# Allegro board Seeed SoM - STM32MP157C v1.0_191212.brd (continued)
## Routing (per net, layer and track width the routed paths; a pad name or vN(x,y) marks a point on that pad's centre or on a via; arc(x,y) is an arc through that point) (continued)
SDMMC3_D1: length 24.5
  TOP w0.089: U3.D9 13.01,15.82 13.01,15.2 12.69,14.88 v1(12.69,14.87)
  LAYER_3 w0.089: v1(19.87,26.53) 19.6,26.26 19.59,26.26 19.56,26.23 19.3,26.23 19.29,26.24 16.89,26.24 16.73,26.41 15,26.41 14.75,26.16 v1(14.5,26.16)
  LAYER_5 w0.089: v1(14.5,26.16) 14.5,25.82 14.41,25.74 13.86,25.74 13.77,25.65 13.77,25.47 13.86,25.38 14.41,25.38 14.5,25.29 14.5,25.11 14.41,25.02 13.86,25.02 13.77,24.94 13.77,24.76 13.86,24.67 14.41,24.67 14.5,24.58 14.5,24.22 13.31,23.03 13.31,22.78 13.4,22.69 13.53,22.69 13.62,22.6 13.62,22.42 13.53,22.33 13.4,22.33 13.31,22.24 13.31,21.99 12.46,21.13 12.46,18.27 13.01,17.72 13.01,15.19 v1(12.69,14.87)
  BOTTOM w0.089: v1(19.87,26.53) 19.87,26.29 19.83,26.24 J2.62
SDMMC3_D2: length 24.5
  TOP w0.089: U3.A7 11.88,20.04 11.33,20.6 11.33,20.91 11.42,21 11.73,21 11.82,21.09 11.82,21.27 11.73,21.36 11.42,21.36 11.33,21.45 11.33,22.76 10.62,23.46 10.62,23.92 10.49,24.05 8.83,24.05 8.74,24.14 8.74,24.46 8.83,24.55 9.63,24.55 9.77,24.69 9.77,25.11 9.86,25.19 10.04,25.19 10.13,25.11 10.13,24.67 10.22,24.58 11,24.58 11.16,24.73 v1(11.16,25.19)
  LAYER_3 w0.089: v1(20.22,24.98) 20.22,24.63 20.07,24.48 11.71,24.48 11.33,24.86 11.33,25.01 v1(11.16,25.19)
  BOTTOM w0.089: J2.64 20.23,24.98 v1(20.22,24.98)
SDMMC3_D3: length 24.5
  TOP w0.089: U3.D10 13.38,14.96 v1(13.49,14.85)
  LAYER_3 w0.089: v1(20.52,26.41) 20.52,26.1 19.82,25.39 19.31,25.39 19.22,25.48 19.22,25.73 19.13,25.82 18.95,25.82 18.86,25.73 18.86,25.48 18.78,25.39 18.6,25.39 18.51,25.48 18.51,25.73 18.42,25.82 18.24,25.82 18.15,25.73 18.15,25.48 18.06,25.39 16.88,25.39 16.79,25.3 16.79,25.17 16.7,25.09 16.52,25.09 16.43,25.17 16.43,25.3 16.35,25.39 16.13,25.39 v1(15.83,25.7)
  LAYER_5 w0.089: v1(15.83,25.7) 15.65,25.52 15.65,25.52 15.19,25.06 15.19,24.79 15.28,24.7 15.38,24.7 15.47,24.61 15.47,24.43 15.38,24.34 15.28,24.34 15.19,24.25 15.19,23.97 14.71,23.49 14.71,21.76 14.62,21.67 14.5,21.67 14.41,21.58 14.41,21.41 14.5,21.32 14.62,21.32 14.71,21.23 14.71,20.89 14.56,20.74 14.1,20.74 14,20.64 14,18.78 14.09,18.69 14.22,18.69 14.3,18.6 14.3,18.42 14.22,18.33 14.09,18.33 14,18.25 14,18.07 14.09,17.98 14.22,17.98 14.3,17.89 14.3,17.71 14.22,17.62 14.09,17.62 14,17.53 14,17.36 14.09,17.27 14.22,17.27 14.3,17.18 14.3,17 14.22,16.91 14.09,16.91 14,16.82 14,15.7 13.49,15.19 v1(13.49,14.85)
  BOTTOM w0.089: v1(20.52,26.41) 20.52,26.16 20.63,26.05 20.63,25.76 20.48,25.61 20.48,25.41 20.63,25.26 J2.66
SPI1_CLK: length 32.7
  TOP w0.076: v1(9.07,30.24) 8.83,30.24 8.75,30.17 8.41,30.17
  TOP w0.089: U3.G3 9.63,14.7 8,14.7 5.39,17.31 5.39,27.37 4.96,27.8 4.96,29.45 5.67,30.17 8.41,30.17
  BOTTOM w0.089: J2.40 15.43,24.79 13.57,26.65 13.57,28.85 13.09,29.33 11.54,29.33 11.33,29.53 9.78,29.53 v1(9.07,30.24)
SPI1_MISO: length 26.2
  TOP w0.089: U3.G1 7.99,14.45 5.21,17.24 5.21,25.81 v1(4.85,26.18)
  LAYER_3 w0.089: v1(13.21,26.78) 12.59,27.4 9.43,27.4 8.59,26.56 7.27,26.56 6.89,26.18 v1(4.85,26.18)
  BOTTOM w0.089: v1(13.21,26.78) 13.38,26.61 13.38,26.57 15.03,24.92 J2.38
SPI1_MOSI: length 21
  TOP w0.089: v1(11.02,13.79) 10.86,13.79 10.52,13.45 U3.J4
  LAYER_5 w0.089: v1(10.21,26.86) 10.21,26.52 10.25,26.48 10.25,26.26 9.74,25.75 9.74,24.71 9.25,24.22 9.25,21.46 9.66,21.05 9.66,20.06 9.48,19.88 9.48,18.46 10.01,17.92 10.01,14.8 v1(11.02,13.79)
  BOTTOM w0.089: J2.36 14.63,25.04 13.44,26.23 10.84,26.23 v1(10.21,26.86)
SPI5_CLK: length 26.8
  TOP w0.089: U3.Y11 13.71,8.13 13.71,8.26 v1(13.78,8.33)
  LAYER_5 w0.089: v1(13.78,8.33) 13.96,8.16 13.96,8.03 14.46,7.53 18.11,7.53 18.93,8.35 18.93,9.04 19.21,9.32 19.21,16.81 18.37,17.64 18.37,20.88 17.95,21.3 17.3,21.3 16.95,21.65 16.95,25.57 v1(17.13,25.75)
  BOTTOM w0.089: J2.46 16.63,25.23 16.95,25.55 16.95,25.57 v1(17.13,25.75)
SPI5_MISO: length 27.1
  TOP w0.089: U3.W4 v2(10.37,8.45)
  GND02 w0.089: v1(9.59,5.14) 9.59,5.38 9.6,5.4 9.6,7.68 v2(10.37,8.45)
  LAYER_6 w0.089: v1(16.09,23.08) 16.09,18.16 13.11,15.18 13.11,14.21 12.86,13.96 11.6,13.96 11.46,14.1 10.81,14.1 9.59,12.87 v1(9.59,5.14)
  BOTTOM w0.089: v1(16.09,23.08) 16.09,23.33 16.23,23.46 J2.44
SPI5_MOSI: length 24.8
  TOP w0.089: v1(15.13,8.37) 15.13,8.13 15.13,8.12 15.13,7.7 U3.AA14
  LAYER_5 w0.089: v1(15.13,8.37) 15.3,8.2 15.32,8.2 15.55,7.97 18.04,7.97 18.57,8.5 18.57,9.19 18.85,9.47 18.85,16.48 17.86,17.47 17.86,18.18 16.72,19.32 16.72,25.46 16.68,25.49 v1(16.68,25.74)
  BOTTOM w0.089: v1(16.68,25.74) 16.51,25.56 16.51,25.47 15.83,24.79 J2.42
STLINK_SWCLK: length 32.1
  TOP w0.089: U3.B20 18.63,17.2 18.63,17.9 18.63,17.91 18.63,18.79 19.37,19.53 19.37,20.35 19.54,20.52 19.54,20.89 20.27,21.63 21.01,21.63 21.75,22.37 21.75,24.48 22.1,24.83 22.1,26.97 20.1,28.97 20.1,32.02 19.59,32.53 19.59,34.43 19.08,34.94 12.26,34.94 11.75,34.43 10.95,34.43 v1(10.7,34.69)
  BOTTOM w0.089: v1(10.7,34.69) 11.02,34.36 J4.54
STLINK_SWDIO: length 32.2
  TOP w0.089: U3.C20 18.63,16.7 18.98,16.7 19.13,16.85 19.13,17.79 19.31,17.97 19.31,19.09 20.02,19.8 20.02,20.48 20.18,20.64 20.18,21.16 20.43,21.4 21.09,21.4 21.95,22.27 21.95,24.43 22.28,24.76 22.28,28.31 20.48,30.12 20.48,31.89 19.84,32.53 19.84,34.43 19.08,35.2 11.86,35.2 v1(11.42,34.75)
  BOTTOM w0.089: J4.52 v1(11.42,34.75)
STUSB1600_IRQOUTN: length 16.8
  TOP w0.089: v1(11.31,10.76) 11.11,10.95 U3.P4
  LAYER_5 w0.089: v1(11.31,10.76) 11.06,10.76 10.42,11.4 10.42,11.86 9.15,13.13 9.15,16.32 8.16,17.31 8.16,19.57 8.03,19.7 8.03,20.06 7.55,20.54 7.55,22.8 v1(7.78,23.03)
  BOTTOM w0.089: v1(7.78,23.03) 8.63,23.88 J2.6
TIM4_CH3: length 38.3
  TOP w0.089: U3.L3 9.63,12.21 7.28,12.21 v1(7.22,12.14)
  LAYER_3 w0.089: v1(14.74,34.08) 14.36,34.46 14.1,34.46 13.77,34.13 13.77,33.9 13.16,33.29 5.47,33.29 5.03,32.86 3.92,32.86 v1(3.69,32.63)
  LAYER_5 w0.089: v1(3.69,32.63) 4.09,32.22 4.09,22.95 5.01,22.04 5.01,16.53 5.71,15.83 5.71,13.65 v1(7.22,12.14)
  BOTTOM w0.089: v1(14.74,34.08) 14.74,33.83 14.62,33.71 J4.36
TIM4_CH4: length 33.8
  TOP w0.089: U3.J2 7.8,13.45 7.75,13.5 7.53,13.5 v1(7.35,13.69)
  LAYER_3 w0.089: v1(4.81,32.53) 6.41,32.53 6.99,33.11 13.26,33.11 v1(14.23,34.08)
  LAYER_5 w0.089: v1(7.35,13.69) 6.84,14.2 6.84,15.28 5.39,16.73 5.39,22.27 4.5,23.16 4.5,32.22 v1(4.81,32.53)
  BOTTOM w0.089: v1(14.23,34.08) 14.23,33.83 14.22,33.82 J4.38
USART1_CTS: length 27.1
  TOP w0.089: v1(11.08,15.08) 10.59,14.58 10.51,14.58 U3.G4
  LAYER_3 w0.089: v1(18.7,27.45) 18.7,27.7 18.39,28 17.74,28 17.74,28.01 10.62,28.01 v1(10.44,28.18)
  LAYER_5 w0.089: v1(10.44,28.18) 10.8,28.18 11.49,27.5 11.49,26.89 11.47,26.87 11.47,23.82 11.21,23.56 11.21,22.38 11.75,21.84 11.75,19.43 11.36,19.05 11.36,15.36 v1(11.08,15.08)
  BOTTOM w0.089: J2.56 18.63,26.89 18.7,26.96 v1(18.7,27.45)
USART1_RTS: length 45.1
  TOP w0.089: v1(1.88,31.79) 1.88,23.84 4.65,21.07 4.65,16.88 7.88,13.66 9.08,13.66 U3.H2
  LAYER_3 w0.089: v1(1.88,31.79) 5.79,31.79 7.44,30.14 8.18,30.14 9.39,28.93 18.48,28.93 19.42,27.99 19.42,27.73 19.44,27.72 v1(19.44,27.47)
  BOTTOM w0.076: 19.08,26.81 19.03,26.76 19.03,25.87
  BOTTOM w0.089: v1(19.44,27.47) 19.44,27.21 19.25,27.02 19.25,26.98 19.08,26.81 ; 19.03,25.87 J2.58
USART1_RX: length 43.5
  TOP w0.089: U3.H1 7.86,13.95 4.86,16.96 4.86,22.12 2.21,24.76 2.21,30.86 2.2,30.88 v1(2.2,31.13)
  LAYER_3 w0.089: v1(18.29,27.14) 18.95,27.14 19.11,27.3 19.11,27.88 18.79,28.2 18.09,28.2 18.06,28.17 17.81,28.17 17.78,28.2 11.28,28.2 10.93,28.55 9.39,28.55 8.03,29.91 7.22,29.91 6.06,31.07 5.62,31.07 5.18,31.51 2.33,31.51 2.2,31.38 v1(2.2,31.13)
  BOTTOM w0.089: J2.54 18.23,26.66 18.22,26.67 18.22,26.82 18.29,26.9 v1(18.29,27.14)
USART1_TX: length 26.9
  TOP w0.089: v1(11.28,14.44) 11.05,14.21 11.05,14.21 10.97,14.13 10.92,14.13 10.49,13.7 10.13,13.7 U3.J3
  LAYER_5 w0.089: v1(11.28,14.44) 10.75,14.44 10.29,14.91 10.29,20.67 9.43,21.53 9.43,24.12 9.92,24.61 9.92,25.63 10.69,26.4 10.69,26.74 10.6,26.84 v1(10.6,27.09)
  LAYER_6 w0.089: v1(10.6,27.09) 10.84,27.09 11.03,27.27 17.68,27.27 v1(17.99,27.58)
  BOTTOM w0.089: J2.52 17.83,24.79 17.99,24.95 v1(17.99,27.58)
USART2_RX: length 9.4
  TOP w0.089: v1(7.87,22.32) 7.7,22.14 7.7,22.14 6.63,21.07 6.63,19.62 6.42,19.41 6.42,18.56 7.87,17.11 7.87,16.49 8.15,16.21 9.13,16.21 U3.D2
  BOTTOM w0.089: v1(7.87,22.32) 7.87,22.26 7.83,22.22 J2.1
USART2_TX: length 21.9
  TOP w0.089: U3.D7 v1(11.88,15.65)
  LAYER_3 w0.089: v1(7.15,25.96) 7.32,26.13 11.16,26.13 11.59,26.57 11.59,26.61 v1(11.77,26.79)
  LAYER_5 w0.089: v1(11.88,15.65) 12.11,15.88 12.11,21.36 12.32,21.58 12.32,22.45 12.49,22.62 12.49,25.41 11.77,26.13 v1(11.77,26.79) ; v1(7.15,25.96) 7.15,25.71 8.51,24.35 v1(8.51,23.32)
  BOTTOM w0.089: J2.3 8.23,22.79 8.51,23.07 v1(8.51,23.32)
USB1_N: length 72.3
  TOP w0.089: U3.AB17 16.63,6.71 16.63,5.77 17.91,4.49 17.91,4.13
  TOP w0.114: v1(17.71,2.1) 17.91,2.3 17.91,4.13
  LAYER_6 w0.135: v1(17.71,2.1) 17.9,1.92 17.9,1.24 18.46,0.68 23.17,0.68 24.08,1.58 25.81,1.58 30,5.77 30,18.29 31.18,19.47 31.18,30.96 28.15,33.98 24.39,33.98 22.84,35.53 9.57,35.53 9.35,35.76 9.35,36.23 v1(9.53,36.41)
  BOTTOM w0.114: J4.61 9.42,35.82 9.36,35.88 9.36,36.24 v1(9.53,36.41)
USB1_P: length 72.2
  TOP w0.089: 18.22,4.16 18.22,4.54 17.79,4.96 17.79,5.09 17.94,5.24 17.94,5.32 17.76,5.5 17.63,5.5 17.5,5.37 17.38,5.37 16.88,5.87 U3.AC17
  TOP w0.114: 18.22,4.16 18.19,4.13 18.19,2.3 v1(18.39,2.1)
  LAYER_6 w0.135: v1(8.85,36.41) 9.03,36.23 9.03,35.63 9.44,35.22 9.79,35.22 10.01,34.99 10.32,34.99 10.55,35.22 11.74,35.22 11.88,35.09 11.88,34.9 12.01,34.76 12.28,34.76 12.42,34.9 12.42,35.09 12.55,35.22 13.22,35.22 13.45,34.99 13.76,34.99 13.99,35.22 22.71,35.22 24.26,33.67 28.02,33.67 30.87,30.83 30.87,19.6 29.69,18.42 29.69,5.9 25.68,1.9 23.95,1.9 23.04,0.99 18.59,0.99 18.21,1.37 18.21,1.92 v1(18.39,2.1)
  BOTTOM w0.114: v1(8.85,36.41) 9.08,36.18 9.08,35.88 9.02,35.82 J4.63
USB2_N: length 72.2
  TOP w0.089: U3.AB16 16.12,6.69 16.12,5.29 16.95,4.46 16.95,4.11
  TOP w0.114: v1(19.03,1.36) 18.9,1.5 17.31,1.5 16.95,1.86 16.95,4.11
  LAYER_6 w0.135: v1(19.03,1.36) 19.18,1.51 21.15,1.51 21.98,2.34 21.98,6.6 20.59,7.99 20.59,16.45 22.51,18.37 26.98,18.37 29.68,21.07 29.68,28.87 25.81,32.74 14.09,32.74 14.08,32.74 9.01,32.74 8.2,33.56 8.2,36.23 v1(8.38,36.41)
  BOTTOM w0.114: J4.67 8.22,35.82 8.16,35.88 8.16,36.19 v1(8.38,36.41)
USB2_P: length 72.1
  TOP w0.089: U3.AC16 16.38,5.38 17.23,4.54 17.23,4.41
  TOP w0.114: 17.23,4.41 17.23,3.95 17.3,3.88 17.51,3.88 17.59,3.8 17.59,3.5 17.51,3.42 17.35,3.42 17.23,3.29 17.23,3.06 17.3,2.99 17.48,2.99 17.58,2.89 17.58,2.61 17.51,2.53 17.37,2.53 17.23,2.39 17.23,1.97 17.42,1.77 18.86,1.77 v1(19.02,1.93)
  LAYER_6 w0.135: v1(7.7,36.41) 7.88,36.23 7.88,35.4 7.75,35.27 7.58,35.27 7.45,35.13 7.45,34.87 7.58,34.73 7.75,34.73 7.88,34.6 7.88,33.43 8.88,32.43 13.96,32.43 13.96,32.43 25.68,32.43 29.37,28.74 29.37,21.2 26.85,18.69 22.38,18.69 20.28,16.58 20.28,7.86 21.66,6.48 21.66,2.47 21.02,1.83 19.12,1.83 v1(19.02,1.93)
  BOTTOM w0.114: v1(7.7,36.41) 7.88,36.23 7.88,35.88 7.82,35.82 J4.69
VREF+: length 36.8
  TOP w0.203: U3.R4 10.7,10.45 v1(10.75,10.4)
  PWR_4 w0.305: v1(15.17,34.16) 15.17,33.8 14.66,33.29 12.22,33.29 11.33,32.4 11.33,28.34 10.7,27.7 9.55,27.7 9.17,27.32 9.17,26.37 7.24,24.43 7.24,20.95 9.07,19.11 9.07,18.58 9.81,17.85 9.81,10.91 10.32,10.4 v1(10.75,10.4)
  BOTTOM w0.203: J4.31 15.42,34.45 15.39,34.42 15.39,34.38 v1(15.17,34.16)
  BOTTOM w0.254: v1(10.75,10.4) 10.75,10.43
  BOTTOM w0.381: 10.19,10.43 10.73,10.43 v1(10.75,10.4) ; 10.19,10.43 10.06,10.3 R94.2 ; 10.19,10.43 10.29,10.53 C47.1
VREF_DDR: length 50.4
  TOP w0.152: v1(33.52,29.64) U2.16
  TOP w0.203: v1(18.47,5.96) 18.38,6.05 U3.AC20
  TOP w0.305: U6.H1 30.28,17.02 30.46,17.21 v3(30.46,17.61) ; U6.M8 v1(26.67,9.03)
  TOP w0.381: v1(33.52,29.64) 33.81,29.35 C201.1 ; v1(26.9,6.21) 26.95,6.16 C53.1 ; C54.1 30.13,18 30.46,17.67 v3(30.46,17.61)
  LAYER_5 w0.381: v1(33.52,29.64) 33.52,20.3 31.15,17.93 30.77,17.93 v3(30.46,17.61) 30.14,17.3 30.14,11.64 27.51,9.01 ; 27.51,9.01 27.51,6.82 v1(26.9,6.21) 26.62,5.93 26.62,3.14 24.55,1.07 21.89,1.07 v1(21.61,1.35) ; 27.51,9.01 27.49,9.03 v1(26.67,9.03)
  BOTTOM w0.381: v1(21.61,1.35) 20.26,1.35 19.03,2.58 19.03,3.81 19.11,3.89 19.11,5.22 18.72,5.61 C27.1 18.47,5.63 v1(18.47,5.96)
VTT_DDR: length 78.9
  TOP w0.152: U2.14 33.43,28.84
  TOP w0.381: v1(35.46,27.66) 34.88,28.24 C202.1 34.32,28.27 33.75,28.84 33.43,28.84 ; R38.2 29.87,4.56 v1(29.67,4.36)
  LAYER_5 w0.381: v1(33.56,16.91) 33.95,16.91 34.12,16.74 36.29,16.74 36.89,16.15 36.89,6.09 35.72,4.92 30.23,4.92 v1(29.67,4.36)
  BOTTOM w0.381: R24.2 R22.2 R19.2 ; R24.2 C63.1 ; R24.2 R26.2 ; R19.2 C61.1 C59.1 ; R19.2 R17.2 ; R29.2 R119.2 R27.2 ; R29.2 28.1,6.07 27.71,5.69 C69.1 ; R29.2 R33.2 R18.2 R21.2 25.07,6.74 ; R20.2 R32.2 R40.2 ; R20.2 27.54,17.32 C62.1 ; R20.2 R17.2 ; 25.07,6.74 25.07,6.29 25.05,6.26 C60.1 C67.1 C69.1 ; 25.07,6.74 R28.2 R23.2 R25.2 ; R40.2 29.45,17.32 29.44,17.32 C68.1 C62.1 ; R40.2 R37.2 R39.2 R36.2 R35.2 v1(33.56,16.91) R34.2 33.94,17.32 33.94,17.32 C70.1 32.87,17.89 32.59,18.17 C93.1 C94.1 32.59,20.13 35.46,23 v1(35.46,27.66) ; C69.1 C66.1 29.48,5.23 C91.1 29.67,4.36 v1(29.67,4.36) 29.67,4.36 C92.1 ; R30.2 R26.2 ; R26.2 22.97,17.32 22.89,17.39 C65.1 ; R25.2 R31.2 ; R25.2 22.76,6.34 23.27,5.83 C64.1 ; R17.2 26.58,17.32 C59.1 ; C62.1 C59.1
N3275089: length 4.3
  TOP w0.127: R13.1 27.91,5.52 27.49,5.94 27.49,9.04 U6.L8
N3282469: length 9.2
  TOP w0.089: v1(5.85,35.47) 6.61,35.47 9.99,32.1 9.99,30.42 10.79,29.62 U8.A6
  BOTTOM w0.089: v1(5.85,35.47) 5.6,35.47 5.55,35.53 R147.1
N3282544: length 1.9
  TOP w0.089: U8.C2 12.25,27.37 12.25,26.78 v1(12.27,26.76)
  BOTTOM w0.089: v1(12.27,26.76) 12.27,27.3 12.48,27.5 C180.1
N3283232: length 10.2
  TOP w0.076: U8.A3 10.81,28.12 10.57,27.88 10.32,27.88 8.59,29.61
  TOP w0.089: v1(5.85,26.51) 5.85,29.02 6.43,29.61 8.59,29.61
  BOTTOM w0.089: v1(5.85,26.51) 5.35,26.51 R136.2 4.69,26.49 4.68,26.5 R125.2
N3283236: length 7.3
  TOP w0.076: 10.05,28.63 10.63,28.63 10.64,28.62 U8.A4
  TOP w0.089: 10.05,28.63 8.72,29.96 6.22,29.96 6.09,29.84 v1(5.85,29.84)
  BOTTOM w0.089: v1(5.85,29.84) 5.82,29.81 5.7,29.81 5.67,29.84 R137.2 4.69,29.84 4.68,29.85 R126.2
N3283240: length 9.1
  TOP w0.076: U8.A5 10.73,29.12 10.44,29.4
  TOP w0.089: v1(5.77,32.91) 8.39,32.91 9.58,31.72 9.58,30.27 10.44,29.4
  BOTTOM w0.089: v1(5.77,32.91) 5.73,32.91 5.7,32.93 R138.2 4.69,32.93 4.68,32.94 R127.2
N3283244: length 13.4
  TOP w0.076: 9.31,28.29 10.23,27.38 11.26,27.38 U8.B2
  TOP w0.089: 9.31,28.29 8.38,29.23 6.89,29.23 6.35,28.69 6.35,23.74 v1(6.15,23.54)
  BOTTOM w0.089: v1(6.15,23.54) 5.9,23.54 5.72,23.35 R139.2 4.69,23.35 4.68,23.34 R128.2
N3283248: length 12
  TOP w0.076: U8.B3 11.25,27.86 10.9,27.86 10.72,27.68 10.59,27.68
  TOP w0.089: v1(5.87,24.96) 6.18,25.26 6.18,28.87 6.74,29.43 8.54,29.43 10.3,27.68 10.59,27.68
  BOTTOM w0.089: v1(5.87,24.96) 5.83,24.92 R140.2 4.7,24.92 4.68,24.9 R129.2
N3283252: length 8.9
  TOP w0.076: U8.B4 11.25,28.36 10.68,28.36 10.57,28.48 10.3,28.48 10.29,28.46 9.99,28.46 8.67,29.78 8.41,29.78
  TOP w0.089: 8.41,29.78 6.3,29.78 6.17,29.66 6.16,29.66 5.29,28.79 v1(5.29,28.54)
  BOTTOM w0.089: R130.2 4.68,28.12 4.7,28.14 R141.2 v1(5.29,28.54)
N3283256: length 9.6
  TOP w0.076: 9.91,29.05 10.18,28.78 10.83,28.78 10.9,28.86 11.25,28.86 U8.B5
  TOP w0.089: 9.91,29.05 9.38,29.58 9.38,31.31 9.12,31.56 5.92,31.56 v1(5.74,31.39)
  BOTTOM w0.089: v1(5.74,31.39) 5.72,31.39 5.69,31.36 R142.2 4.96,31.36 4.92,31.41 R131.2
N3283260: length 10.3
  TOP w0.076: 9.78,30.34 10.75,29.38 11.26,29.38 U8.B6
  TOP w0.089: v1(5.87,34.56) 7.07,34.56 9.78,31.84 9.78,30.34
  BOTTOM w0.089: R132.2 4.65,34.59 4.66,34.58 R143.2 5.85,34.58 v1(5.87,34.56)
N3283264: length 13.6
  TOP w0.076: U8.M5 16.28,29.12 15.95,28.79 15.93,28.79 v1(15.76,28.62)
  BOTTOM w0.076: 17.15,29.96 17.07,29.96 16.98,29.87 16.98,29.76 17.2,29.54 17.2,29.43 17.1,29.32 16.99,29.32 16.77,29.55 16.66,29.55 16.55,29.44 16.55,29.33 16.77,29.11 16.77,29 16.66,28.89 16.56,28.89 16.33,29.12 16.23,29.12 15.93,28.82 15.93,28.79 v1(15.76,28.62)
  BOTTOM w0.089: R133.2 R144.2 21.46,27.78 21.37,27.87 21.37,28.12 21.28,28.21 20.9,28.21 20.81,28.3 20.81,28.48 20.9,28.57 21.28,28.57 21.37,28.66 21.37,29.56 20.96,29.96 19.59,29.96 19.5,29.87 19.5,29.75 19.41,29.66 19.23,29.66 19.14,29.75 19.14,29.87 19.05,29.96 18.87,29.96 18.79,29.87 18.79,29.75 18.7,29.66 18.52,29.66 18.43,29.75 18.43,29.87 18.34,29.96 17.15,29.96
N3283268: length 37.4
  TOP w0.076: v1(15.98,29.4) 16.15,29.57 16.17,29.57 16.22,29.62 U8.M6
  BOTTOM w0.089: 21.7,29.63 21.06,30.27 20.38,30.27 20.29,30.36 20.29,30.92 20.2,31 20.03,31 19.94,30.92 19.94,30.36 19.85,30.27 16.85,30.27 v1(15.98,29.4) ; 21.7,29.63 21.74,29.58 21.74,29.5 ; 21.7,29.63 21.87,29.63 ; R145.2 21.74,29.5 ; 21.74,29.5 21.87,29.63 ; 21.87,29.63 22.69,29.63 22.89,29.43 22.89,28.69 22.98,28.6 23.23,28.6 23.32,28.51 23.32,28.33 23.23,28.24 22.98,28.24 22.89,28.15 22.89,27.98 22.98,27.89 23.23,27.89 23.32,27.8 23.32,27.62 23.23,27.53 22.98,27.53 22.89,27.44 22.89,27.26 22.98,27.18 23.23,27.18 23.32,27.09 23.32,26.91 23.23,26.82 22.98,26.82 22.89,26.73 22.89,26.55 22.98,26.46 23.23,26.46 23.32,26.38 23.32,26.2 23.23,26.11 22.98,26.11 22.89,26.02 22.89,25.84 22.98,25.75 23.23,25.75 23.32,25.66 23.32,25.49 23.23,25.4 22.98,25.4 22.89,25.31 22.89,25.13 22.98,25.04 23.23,25.04 23.32,24.95 23.32,24.78 23.23,24.69 22.98,24.69 22.89,24.6 22.89,24.42 22.98,24.33 23.23,24.33 23.32,24.24 23.32,24.06 23.23,23.98 22.98,23.98 22.89,23.89 22.89,23.71 22.98,23.62 23.23,23.62 23.32,23.53 23.32,23.35 23.23,23.26 22.98,23.26 22.89,23.18 22.89,23 22.98,22.91 23.23,22.91 23.32,22.82 23.32,22.64 23.23,22.55 22.98,22.55 22.89,22.46 22.89,21.58 22.2,20.89 21.7,20.89 21.37,20.56 20.86,20.56 19.36,19.07 17.99,19.07 17.63,18.7 17.63,18.7 16.67,17.75 15.9,17.75 15.42,17.26 13.82,17.26 13.14,16.58 C179.1 R134.2
N3283272: length 2.4
  TOP w0.089: U8.K5 15.5,28.88 v1(15.24,28.62)
  BOTTOM w0.089: v1(15.24,28.62) 15.24,28.37 15.35,28.27 R146.2 R135.2
N3285898: length 1.2
  TOP w0.076: v1(14.97,29.45) 15,29.42 U8.J5
  BOTTOM w0.076: v1(14.97,29.45) 14.79,29.63 14.79,29.73 14.66,29.86 R148.1
N3300775: length 1.1
  TOP w0.152: 29.87,26.81 30.07,27.01 U2.7
N3300820: length 2.5
  TOP w0.381: v1(28.16,23.58) R154.1 v1(27.55,24.18) ; v1(28.76,24.02) 28.95,24.21 L9.2
N3300941: length 0.8
  TOP w0.152: U2.11 31.68,27.29 31.9,27.07
N3301067: length 1.1
  TOP w0.152: 29.75,33.8 29.68,33.73 U2.29
N3301183: length 1.1
  TOP w0.152: U2.25 31.28,33.79
N3302965: length 1.4
  TOP w0.152: U2.40 v1(26.32,30.04)
  BOTTOM w0.381: C208.1 26.5,29.86 v1(26.32,30.04)
N3306561: length 4.4
  TOP w0.089: R153.2 25,25.64 25.3,25.95 25.3,26.74 25.84,27.27 27.46,27.27 27.68,27.48 U2.1
N3308705: length 1.1
  TOP w0.152: U2.33 28.07,33.44 27.84,33.67
N3308709:
  vias: v1(25.3,36.72) v1(25.81,36.72) v1(26.32,36.72) v1(26.83,36.72)
N3309141: length 2.5
  TOP w0.152: 26.37,32.22 26.45,32.22 26.63,32.04 U2.35
  TOP w0.381: R155.1 25.51,33.09 26.37,32.22
N3309849: length 2.1
  TOP w0.152: 26.38,31.2 26.42,31.24 U2.37
  TOP w0.381: R150.2 24.87,31.08 24.92,31.13 25.31,31.13 25.37,31.2 26.38,31.2
N3309984: length 2.4
  TOP w0.152: U2.38 25.52,30.84 25.3,30.62
  TOP w0.381: 25.3,30.62 25.3,30.61 R156.1
N3317349: length 4.5
  TOP w0.203: U3.AB15 15.88,4.51 16.34,4.05 v1(16.34,3.19)
  BOTTOM w0.203: C48.2 16.21,3.19 16.21,3.19 v1(16.34,3.19)
N3317353: length 31.9
  TOP w0.089: U3.AB14 15.65,6.69 15.65,4.34 16.03,3.96 16.03,2.18 v1(16.29,1.92) ; 14.84,15.56 15.02,15.56 15.13,15.68 15.13,16.21 U3.C14
  TOP w0.203: v1(14.39,15.54) 14.81,15.54 14.84,15.56
  LAYER_6 w0.089: v1(16.29,1.92) 16.02,2.19 16.02,3.94 15.83,4.13 14.99,4.13 14.25,3.39 11.97,3.39 9.78,5.58 9.78,10.56 10.22,10.99 10.9,10.99 11.76,11.85 11.76,13.38 12.15,13.76 13.19,13.76 13.39,13.96 13.62,13.96 14.2,14.54 14.5,14.54 14.58,14.63 14.58,15.35 v1(14.39,15.54)
  BOTTOM w0.381: C49.1 14.08,15.54 v1(14.39,15.54) 14.69,15.54 C50.1 14.79,16.43 R95.2
N3322011: length 2.3
  TOP w0.089: U3.C18 17.15,16.45 v1(17.12,16.48) 17.1,16.45 U3.C17
  BOTTOM w0.203: C142.1 C51.1 17.18,16.09 17.12,16.15 v1(17.12,16.48)
N3340590: length 8.8
  TOP w0.203: v1(11.12,8.35) 11.12,8.83 11.35,9.06 11.35,9.57 U3.1H1
  TOP w0.254: v1(10.78,4.11) 11.12,4.11 L5.2
  BOTTOM w0.203: v1(11.12,8.35) 11.12,7.74 10.83,7.44 R94.1
  BOTTOM w0.254: C46.1 11.31,9.06 11.21,8.96 11.21,8.83 11.12,8.75 v1(11.12,8.35)
  BOTTOM w0.381: R94.1 10.83,5.28 10.78,5.23 v1(10.78,4.11) 10.62,3.95 R93.2
N3340594: length 1.2
  TOP w0.381: L5.1 12.04,2.58 12.13,2.49 R12.2
N3362916: length 2
  TOP w0.089: R10.1 21.36,12.84 21.11,13.09 20.02,13.09 U3.K23
N3364394: length 3.9
  TOP w0.089: v1(19.28,5.86) 19.04,5.86 18.63,6.26 18.63,7.12 18.55,7.21 18.28,7.21 18.13,7.35 18.13,7.7 U3.Y19
  BOTTOM w0.089: TP102.1 19.37,5.48 19.28,5.57 v1(19.28,5.86)
N3364398: length 1.1
  TOP w0.089: U3.K20 v1(18.07,12.95)
  BOTTOM w0.127: TP103.1 18.19,13.07 v1(18.07,12.95)
N3364402: length 5.4
  TOP w0.089: v1(17.63,12.94) 17.63,12.31 17.76,12.18 17.83,12.18 18.23,12.18 18.25,12.21 18.63,12.21 U3.L21
  BOTTOM w0.089: v1(17.63,12.94) 17.63,12.7 17.63,12.69 17.63,12.39 17.86,12.16 19.42,12.16 19.73,11.85 TP104.1
N3371131: length 4
  TOP w0.127: OSC1.3 2.1,5.57 3.13,4.54 3.75,4.54 4.07,4.22 C108.1 R4.1
N3371139: length 2.8
  TOP w0.127: OSC1.4 4.54,5.57 4.91,5.2 5.22,5.2 5.22,5.19 v1(5.49,5.19)
  BOTTOM w0.127: v1(5.49,5.19) 5.49,5.02 5.57,4.94 C106.2 R87.2
N3371143: length 4.2
  TOP w0.127: R1.2 4.05,9.42 4.06,9.43 R90.1 3.54,9.77 3.47,9.7 R88.2 ; R1.2 3.77,8.76 3.76,8.75 C107.2 ; R1.2 4.05,8.27 4.28,8.04 OSC1.1
N3374325: length 4.9
  TOP w0.089: U3.AB13 14.63,6.71 14.63,5.81 14.89,5.55 v1(14.89,3.59)
  BOTTOM w0.127: R81.1 R82.1 v1(14.89,3.59)
N3375018: length 7
  TOP w0.089: 6.79,10.56 7.19,10.96 7.47,10.96 7.73,10.71 9.63,10.71 U3.R3
  TOP w0.127: v1(6.15,8.33) 6.15,8.6 6.79,9.24 6.79,10.56
  BOTTOM w0.127: R85.2 v1(6.15,8.33) 6.13,8.31 R83.1
N3375025: length 7.8
  TOP w0.089: v1(6.02,5.99) 6.58,6.54 6.58,7.51 6.96,7.89 6.96,9.13 7.55,9.72 7.96,9.72 7.98,9.7 9.63,9.7 U3.T3
  BOTTOM w0.127: R86.2 6.05,6.01 v1(6.02,5.99) 6.02,5.99 R84.1
N3375486: length 1.1
  TOP w0.203: v1(11.06,11.9) 10.43,11.9 U3.M4
  BOTTOM w0.203: C105.1 11.26,11.95 11.21,11.9 v1(11.06,11.9)
N3376367: length 1.4
  TOP w0.089: U3.AB18 17.56,6.78 v1(17.56,5.96)
  BOTTOM w0.089: R80.1 v1(17.56,5.96)
N3444553: length 4
  TOP w0.127: R2.2 4.66,14.2 4.47,14.02 4.47,13.6 4.28,13.41 C109.1 3.38,13.41 2.83,13.95 2.83,14.03 2.42,14.44 X1.1
N3444560: length 4.4
  TOP w0.127: X1.2 2.04,11.87 2.63,12.46 C110.1 4.33,12.46 4.45,12.35 4.45,11.79 4.58,11.66 R79.1
N3457313: length 4.8
  TOP w0.089: U3.N3 v2(9.87,11.45)
  GND02 w0.089: v1(6.31,11.23) 6.48,11.06 8.56,11.06 8.95,11.45 v2(9.87,11.45)
  BOTTOM w0.089: v1(6.31,11.23) 6.48,11.06 6.48,11.05 6.58,10.95 TP101.1
N3836449: length 3.9
  TOP w0.127: LED2.1 3.02,34.77 3.33,35.09 3.33,35.11 3.59,35.37 3.59,36.43 v1(3.31,36.72)
  BOTTOM w0.127: v1(3.31,36.72) 2.57,35.98 R5.2
N3836598: length 5
  TOP w0.127: v1(2.27,36.77) 2.27,36.5 LED1.1
  BOTTOM w0.127: v1(2.27,36.77) 1.91,36.41 1.91,34.89 2.21,34.59 R7.2 R6.2

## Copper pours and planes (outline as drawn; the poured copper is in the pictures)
3V3 on TOP: 33.43,32.02 32.67,32.02 32.54,32.15 32.54,32.27 33.81,33.54 34.83,33.54 34.95,33.42 34.95,32.91 34.83,32.78 34.19,32.78
3V3 on TOP: 31.91,37.35 33.18,37.35 33.3,37.23 33.3,35.96 33.18,35.83 31.4,35.83 30.64,35.07 30.64,33.29 30.38,33.04 30.38,35.83
3V3 on BOTTOM: 31.78,35.2 31.78,37.1 32.03,37.35 33.05,37.35 33.3,37.1 33.3,35.32 33.05,35.07 31.91,35.07
3V3 on PWR_4: 32.92,37.35 31.91,37.35 31.65,37.1 31.65,34.43 31.14,33.93 20.22,33.93 18.06,31.77 15.14,31.77 14.89,31.51 14.89,31.13 15.14,30.88 15.14,30.37 13.75,28.97 13.75,28.34 13.87,28.21 15.27,28.21 16.92,29.86 20.73,29.86 21.75,30.88 33.43,30.88 34.45,31.89 34.45,33.93 33.3,35.07 33.3,36.97
5V_VIN on TOP: 24.79,32.27 24.79,31.89 24.92,31.77 25.56,31.77 25.81,31.51 26.32,31.51 26.45,31.64 26.45,31.77 25.81,32.4 24.92,32.4
5V_VIN on BOTTOM: 25.56,35.32 25.56,34.56 25.68,34.43 25.68,30.88 26.09,30.47 26.09,29.89 26.52,29.45 27.11,29.45 28.35,28.21 32.16,28.21 32.29,28.34 32.29,30.62 33.3,31.64 33.3,33.29 33.18,33.42 32.54,33.42 32.29,33.16 32.29,32.27 32.16,32.15 29.87,32.15 29.75,32.27 29.75,33.54 30.89,34.69 33.81,34.69 35.08,33.42 35.08,28.34 33.3,26.56 25.81,26.56 24.03,28.34 24.03,33.67 22,35.7 18.7,35.7 18.44,35.96 18.44,36.97 18.83,37.35 23.14,37.35 25.05,35.45 25.43,35.45
GND on TOP: 24.29,29.48 24.29,28.08 24.16,27.96 23.27,27.96 23.14,28.08 23.14,29.35 23.4,29.61 24.16,29.61
GND on TOP: 0.25,0.25 0.25,37.75 37.75,37.75 37.75,0.25 ; 45 cut-outs
GND on TOP: 35.34,32.27 35.34,33.93 35.46,34.05 36.86,34.05 36.99,33.93 36.99,32.27 36.86,32.15 35.46,32.15
GND on TOP: 35.97,26.18 35.97,28.59 35.34,29.23 35.34,31.26 35.46,31.39 36.99,31.39 37.24,31.13 37.24,26.18 37.11,26.05 36.1,26.05
GND on BOTTOM: 32.92,31.77 31.91,30.75 31.91,29.1 31.65,28.85 28.22,28.85 27.72,29.35 27.72,30.75 28.35,31.39 28.35,33.16 27.72,33.8 26.32,33.8 26.06,34.05 26.06,34.81 26.32,35.07 27.72,35.07 27.97,34.81 29.24,34.81 29.62,35.2 29.62,37.48 29.75,37.61 30.89,37.61 31.02,37.48 31.02,35.32 29.37,33.67 29.37,31.77 29.49,31.64 32.03,31.64 32.41,32.02 32.92,32.02
GND on BOTTOM: 0.25,0.25 0.25,37.75 37.75,37.75 37.75,0.25 ; 31 cut-outs
GND on BOTTOM: 29.49,25.29 29.49,22.5 29.75,22.24 30.38,22.24 30.64,22.5 30.64,25.16 30.38,25.42 29.62,25.42
GND on BOTTOM: 32.67,25.29 32.67,23 32.92,22.75 34.19,22.75 34.95,23.51 34.95,25.04 34.45,25.54 32.92,25.54
GND on GND02: 0.25,0.25 0.25,37.75 37.75,37.75 37.75,0.25 ; 2 cut-outs
GND on LAYER_5: 37.75,0.25 0.25,0.25 0.25,37.75 37.75,37.75 ; 52 cut-outs
GND on LAYER_6: 37.75,0.25 0.25,0.25 0.25,37.75 37.75,37.75 ; 22 cut-outs
GND on GND7: 37.75,0.25 0.25,0.25 0.25,37.75 37.75,37.75
VBUS_SW on TOP: 24.03,29.86 24.16,29.99 24.16,30.37 24.03,30.5 23.65,30.5 23.27,30.88 23.27,32.02 23.02,32.27 22.51,32.27 22.38,32.15 22.38,30.5 23.02,29.86
VBUS_SW on LAYER_3: 16.92,34.18 16.92,32.66 17.17,32.4 19.59,32.4 20.6,31.39 23.14,31.39 23.27,31.51 23.27,32.78 23.02,33.04 20.6,33.04 20.1,33.54 18.06,33.54 17.94,33.67 17.94,34.18 17.81,34.31 17.05,34.31
VDD on TOP: 27.84,34.56 28.6,33.8 28.6,33.29 28.86,33.04 29.11,33.29 29.11,34.31 28.6,34.81 28.6,36.34 28.86,36.59 28.86,37.1 28.73,37.23 28.1,37.23 27.84,36.97
VDD on BOTTOM: 12.04,9.11 12.04,9.52 12.15,9.62 15.04,9.62 15.27,9.39 15.27,9.16 15.02,8.91 15.02,7.76 14.41,7.15 12.88,7.15 12.58,7.46 12.58,8.93 12.5,9.01 12.15,9.01
VDD on BOTTOM: 27.97,35.96 27.97,37.1 28.1,37.23 29.11,37.23 29.24,37.1 29.24,35.83 29.11,35.7 28.22,35.7
VDD on PWR_4: 0.25,0.25 0.25,37.75 37.75,37.75 37.75,0.25 ; 3 cut-outs
VDD_CORE on TOP: 28.48,25.16 27.97,25.16 27.72,25.42 27.72,26.18 27.97,26.43 28.22,26.43 29.24,27.45 29.37,27.32 29.37,27.19 28.73,26.56 28.73,25.42
VDD_CORE on PWR_4: 28.86,26.31 28.86,23.77 28.35,23.26 22.13,23.26 19.46,20.59 19.46,16.02 18.06,14.62 15.9,14.62 15.65,14.37 15.65,13.22 16.16,12.72 16.16,10.43 15.78,10.05 15.4,10.05 13.62,11.83 11.97,11.83 11.21,12.59 11.21,14.62 13.75,17.16 17.05,17.16 17.17,17.03 17.4,17.03 17.58,17.21 17.58,18.15 17.05,18.69 17.05,22.5 21.11,26.56 28.6,26.56
VDD_USB on LAYER_5: 25.05,29.23 25.05,29.61 25.18,29.73 26.7,29.73 27.46,28.97 27.46,10.94 26.32,9.8 26.32,4.08 25.94,3.7 25.18,3.7 24.92,3.95 24.92,11.57 25.81,12.46 25.81,28.46
VDDA on LAYER_5: 33.94,23.77 33.94,20.21 30.64,16.91 30.64,11.32 28.1,8.78 28.1,6.87 27.59,6.37 27.59,5.48 27.84,5.22 28.1,5.22 32.67,9.8 32.67,16.65 35.21,19.19 35.21,23.38 34.7,23.89 34.07,23.89
VDDQ_DDR on TOP: 34.19,26.69 34.19,26.31 34.45,26.05 34.95,26.05 35.21,26.31 35.21,27.32 34.95,27.58 34.57,27.58 33.68,28.46 32.67,28.46 32.67,28.21
VDDQ_DDR on TOP: 31.02,26.69 31.02,24.02 31.27,23.77 32.03,23.77 32.16,23.89 32.16,26.18 30.89,27.45 30.79,27.45 30.76,27.42 30.76,26.94
VDDQ_DDR on BOTTOM: 31.02,25.54 31.02,23.89 31.4,23.51 32.03,23.51 32.16,23.64 32.16,25.54 31.91,25.8 31.27,25.8
VDDQ_DDR on PWR_4: 15.78,13.61 15.78,14.24 15.9,14.37 18.19,14.37 19.71,15.89 19.71,20.46 22.13,22.88 30.51,22.88 31.27,23.64 31.27,24.65 33.81,27.19 35.34,27.19 35.46,27.07 35.46,22.5 37.75,20.21 37.75,0.52 37.48,0.25 18.33,0.25 16.29,2.3 16.29,13.1
(no net) on LAYER_3: 37.75,0.25 0.25,0.25 0.25,37.75 37.75,37.75 ; 85 cut-outs
BST_OUT on BOTTOM: 27.59,31.77 27.59,33.16 27.33,33.42 26.45,33.42 26.32,33.29 26.32,31.77 26.57,31.51 27.33,31.51
BST_OUT on LAYER_3: 17.3,35.96 17.68,35.58 23.02,35.58 25.81,32.78 27.33,32.78 27.46,32.91 27.46,34.18 24.29,37.35 17.68,37.35 17.3,36.97
BST_OUT on LAYER_5: 27.46,33.16 27.46,31.51 26.57,30.62 23.52,30.62 23.4,30.75 23.4,32.53 23.52,32.66 25.94,32.66 26.57,33.29 27.33,33.29
N3300775 on TOP: 29.11,25.67 29.24,25.54 30.64,25.54 30.76,25.67 30.76,26.56 30.26,27.07 30.26,27.19 30.23,27.22 30.23,27.32 30.13,27.42 29.98,27.42 29.11,26.56
N3300820 on TOP: 30.76,24.4 30.76,23.89 30.26,23.38 27.72,23.38 27.33,23.77 27.33,24.4 27.46,24.53 30.64,24.53
N3300820 on BOTTOM: 27.33,25.29 27.33,23.77 27.72,23.38 28.73,23.38 28.99,23.64 28.99,25.29 28.73,25.54 27.59,25.54
N3300941 on TOP: 32.92,25.92 32.92,24.15 33.05,24.02 33.81,24.02 33.94,24.15 33.94,26.56 33.18,27.32 31.86,27.32 31.7,27.47 31.63,27.47 31.58,27.42 31.58,27.27
N3301067 on TOP: 30.13,36.21 30.13,33.93 29.87,33.67 29.87,33.29 29.77,33.19 29.77,33.09 29.72,33.04 29.62,33.04 29.37,33.29 29.37,36.34 29.49,36.47 29.87,36.47
N3301183 on TOP: 33.3,34.56 33.3,33.93 33.05,33.67 32.03,33.67 31.53,33.16 31.42,33.16 31.25,32.99 31.17,33.06 31.17,33.14 30.89,33.42 30.89,34.56 31.14,34.81 33.05,34.81
N3308705 on TOP: 25.56,34.43 25.56,33.93 26.06,33.42 27.59,33.42 27.84,33.16 27.97,33.16 28.1,33.04 28.1,33.16 28.22,33.29 28.22,33.67 27.08,34.81 25.94,34.81
N3308709 on TOP: 24.92,36.08 24.92,37.1 25.05,37.23 26.83,37.23 27.33,36.72 27.33,36.21 26.95,35.83 25.18,35.83
N3308709 on BOTTOM: 25.18,36.97 25.05,36.85 25.05,36.21 25.43,35.83 26.95,35.83 27.08,35.96 27.08,36.85 26.95,36.97
N3309141 on TOP: 24.69,33.24 24.69,32.86 24.93,32.62 25.6,32.62 25.61,32.6 25.71,32.6 26.04,32.27 26.17,32.27 26.4,32.05 26.4,32.02 26.62,32.02 26.73,32.12 26.73,32.38 25.76,33.34 24.79,33.34
N3309984 on TOP: 25.81,30.62 25.56,30.37 25.56,30.12 25.3,29.86 24.79,29.86 24.67,29.99 24.67,30.5 24.79,30.62 25.05,30.62 25.3,30.88 26.45,30.88 26.45,30.75 26.32,30.62

Small or netless copper shapes (teardrops, artwork), in the pictures only: 2 on TOP, 1 on BOTTOM

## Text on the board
Ref Des/Silkscreen Top: PWR | USER | Seeed SoM-STM32MP157C | (OZ) | LAYER 1 - PRIMARY SIDE - SIGNAL | LAYER 2 - GROUND PLANE | LAYER 3 - SIGNAL | LAYER 4 - POWER PLANE | LAYER 5 - SIGNAL | LAYER 6 - SIGNAL | LAYER 7 - GROUND PLANE | LAYER 8 - SECONDARY SIDE - SIGNAL | LAYER# | COPPER WEIGHT | HALF+PLATING | IMPEDANCE CONTROL | +/- 10% | 50ohm SINGLE ENDED | TRACE WIDTH | TRACE WIDTH / SPACE | 90ohm DIFFERENTIAL | 100ohm DIFFERENTIAL | 1 | 5 | 5.3/7.0 | 4.5/6.5 | 3.75/7.25 | 4.00/8.00 | LAYER STACK-UP - ALL DIMENSIONS IN INCHES
User.21: (OZ) | LAYER 1 - PRIMARY SIDE - SIGNAL | LAYER 2 - GROUND PLANE | LAYER 3 - SIGNAL | LAYER 4 - SIGNAL | LAYER 5 - SPLIT POWER PLANE | LAYER 6 - SECONDARY SIDE - SIGNAL | LAYER# | COPPER WEIGHT | HALF+PLATING | IMPEDANCE CONTROL | +/- 10% | 50ohm SINGLE ENDED | TRACE WIDTH | TRACE WIDTH / SPACE | 90ohm DIFFERENTIAL | 100ohm DIFFERENTIAL | 1 | 4.75 | 4.5/6.5 | 5.0/7.0 | 3.75/7.25 | 4.00/8.00 | LAYER STACK-UP - ALL DIMENSIONS IN INCHES
User.24: FIGURE | FINISHED_SIZE | 4.0 | DRILL CHART: TOP to GND02 | ALL UNITS ARE IN MILS | TOLERANCE_DRILL | +0.0/-0.0 | PLATED | QTY | 50 | TOTAL HOLES:
User.27: FIGURE | FINISHED_SIZE | 8.0 | 78.74 | DRILL CHART: TOP to BOTTOM | ALL UNITS ARE IN MILS | TOLERANCE_DRILL | +0.0/-0.0 | +3.0/-3.0 | PLATED | QTY | 734 | 77 | 3 | 814 | TOTAL HOLES:
